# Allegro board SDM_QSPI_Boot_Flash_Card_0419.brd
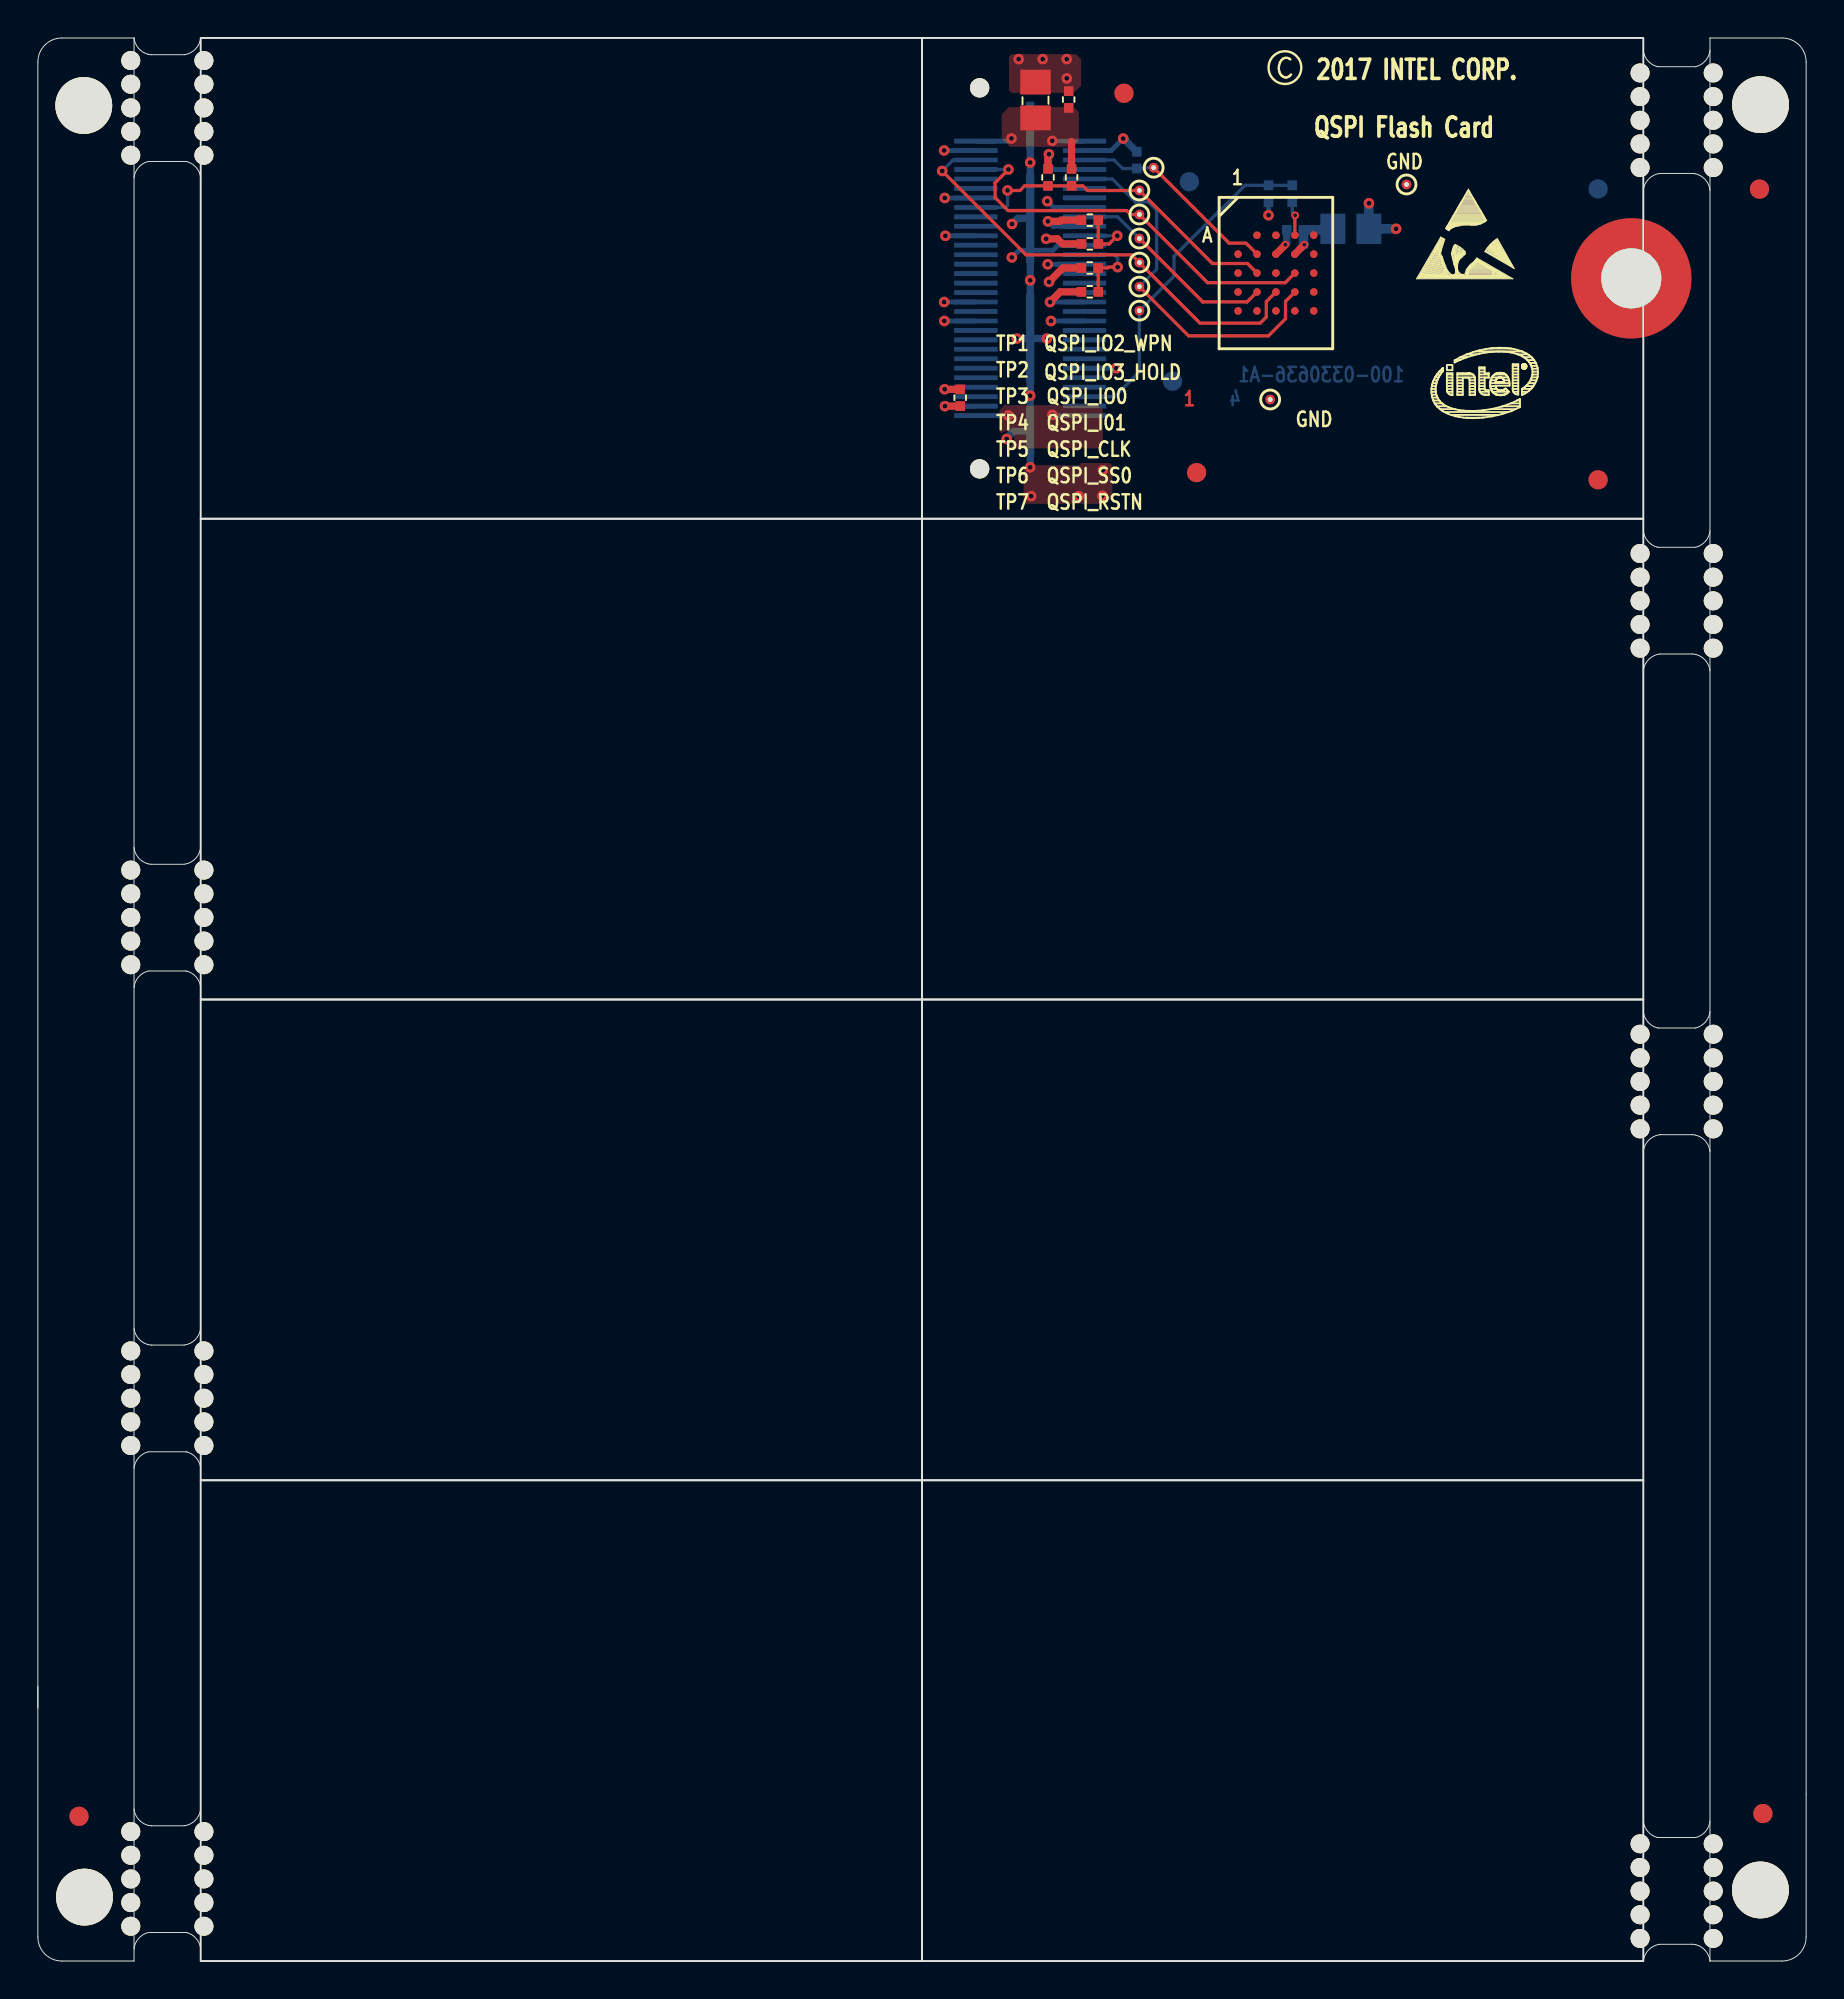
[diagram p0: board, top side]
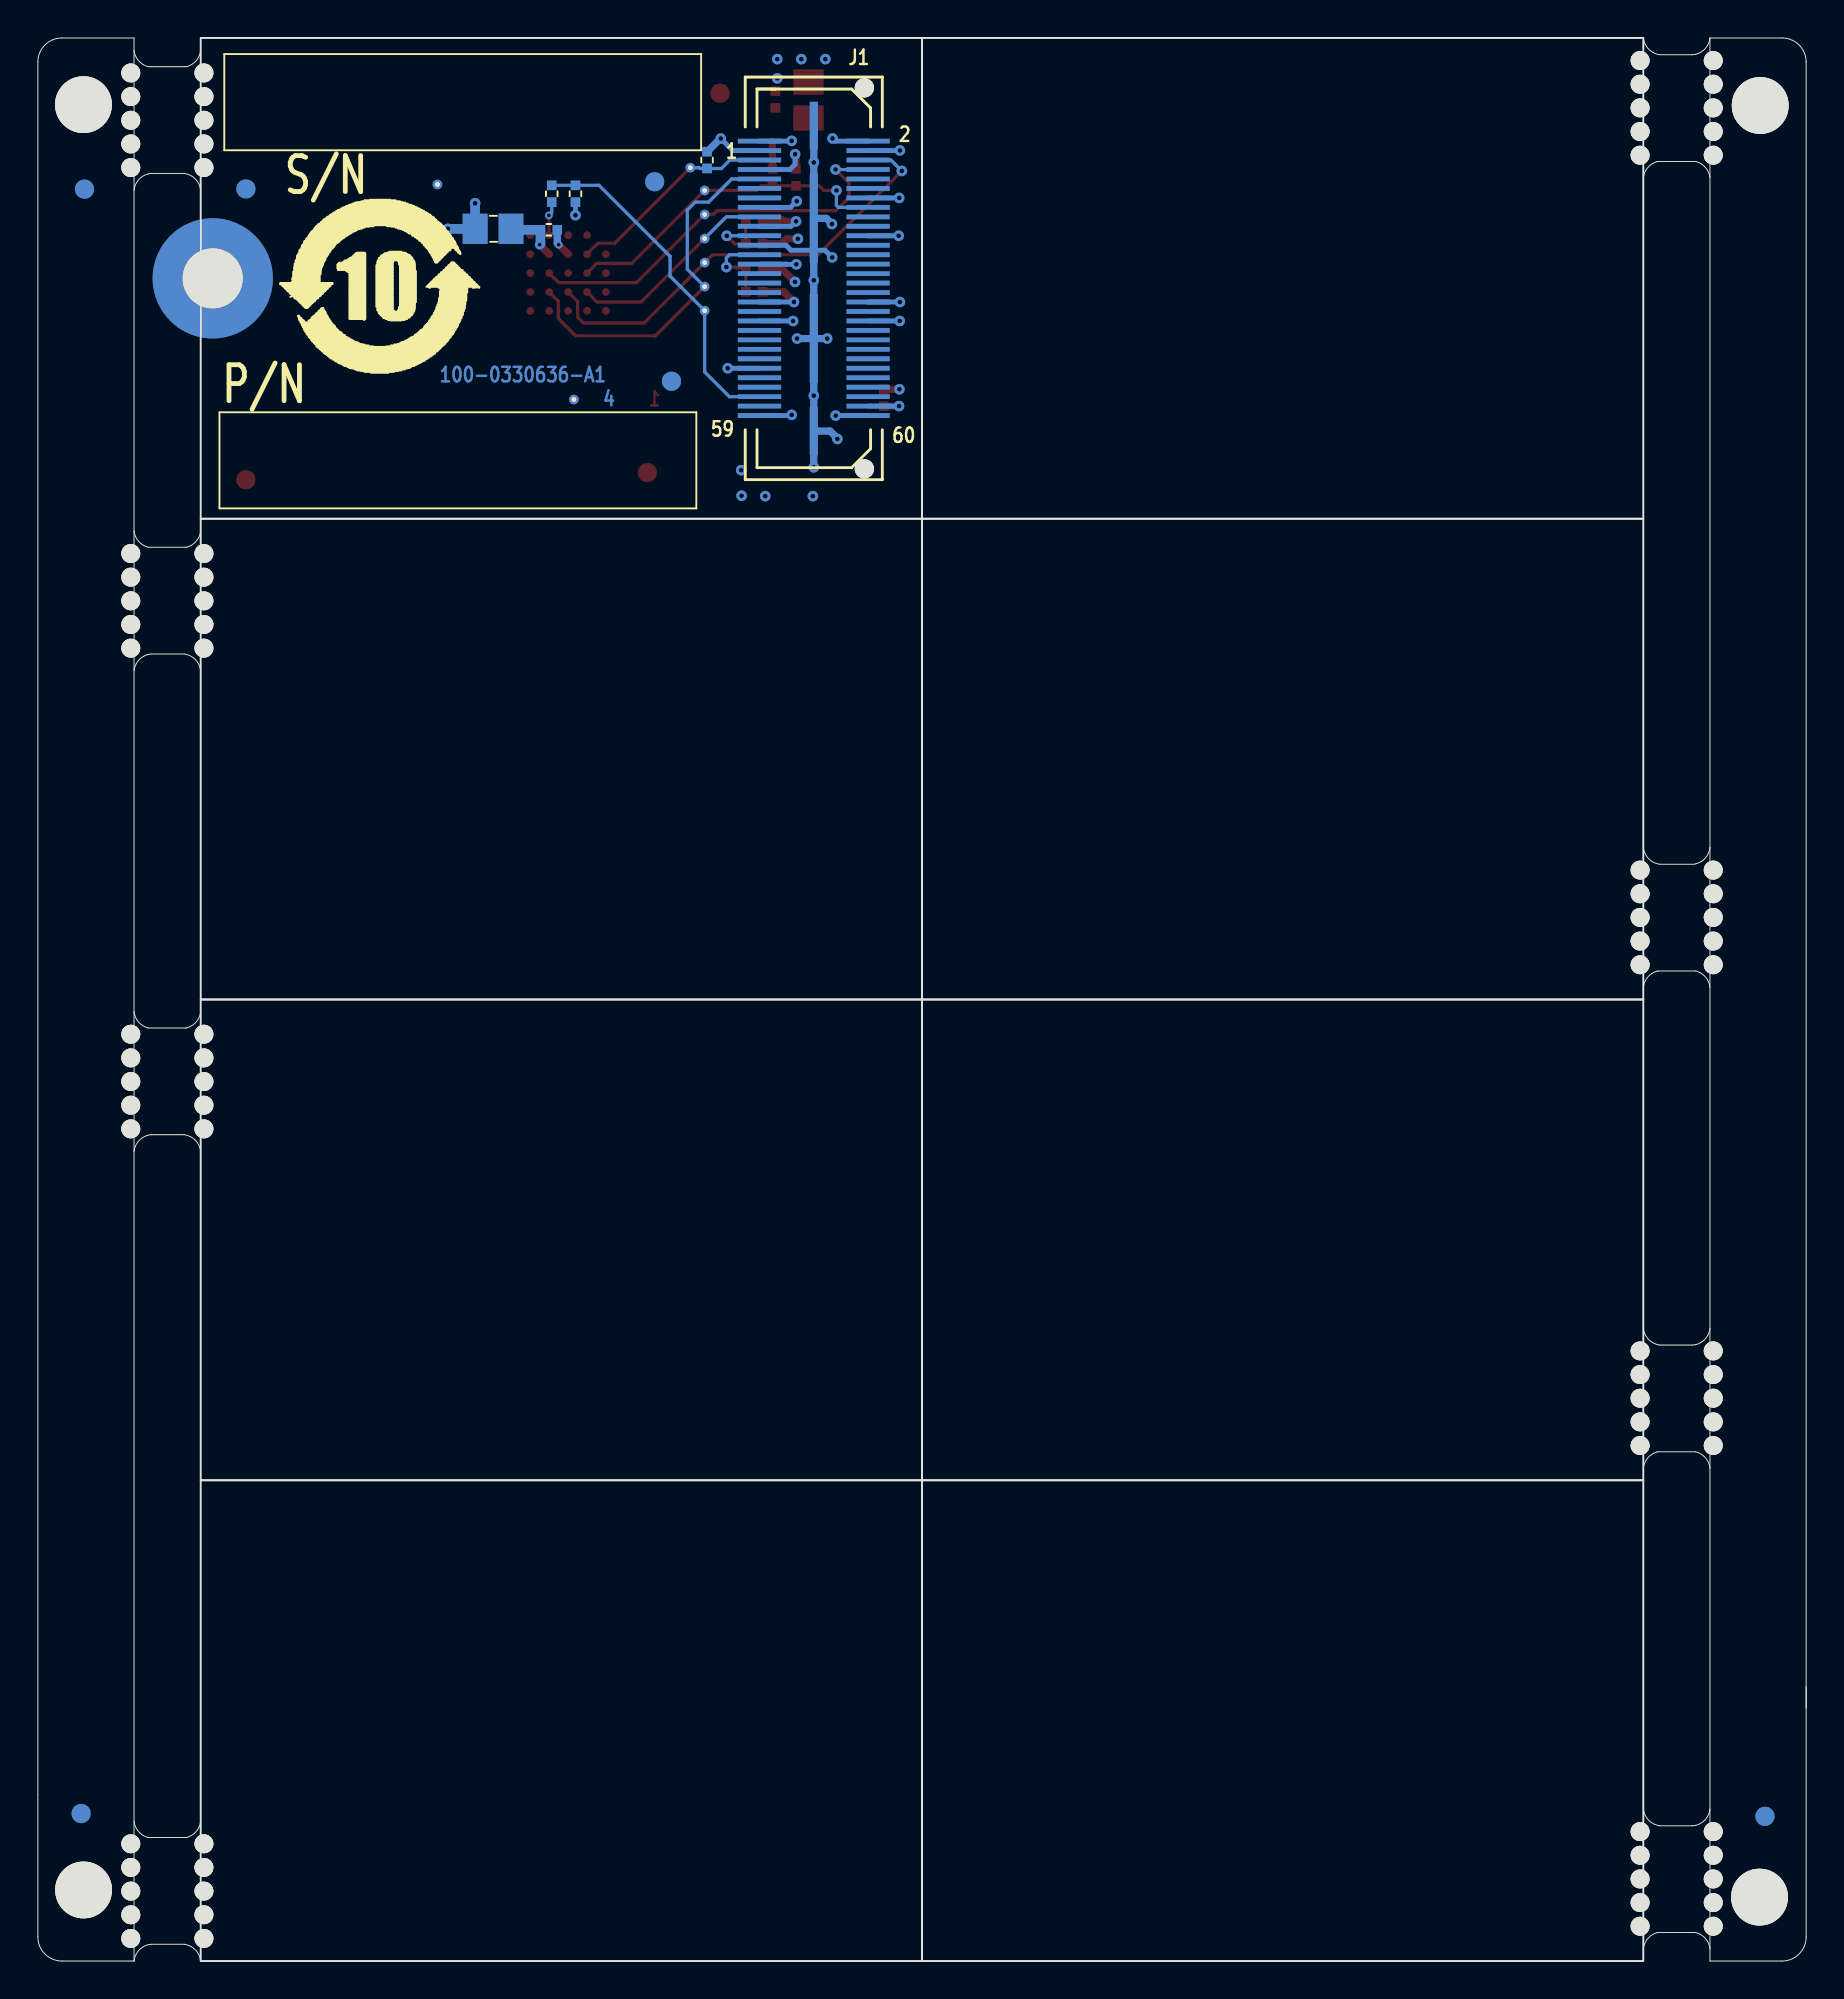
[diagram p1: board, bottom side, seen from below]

Outline 93.4 x 101.61 mm; copper layers: TOP, GND02, POWER03, BOTTOM. Coordinates in mm from the lower left corner of the outline.
Outline path: rectangle 8.6,76.21 46.7,101.61 ; rectangle 8.6,50.81 46.7,76.21 ; rectangle 8.6,25.41 46.7,50.81 ; rectangle 8.6,0.01 46.7,25.41 ; rectangle 46.7,76.21 84.8,101.61 ; rectangle 46.7,50.81 84.8,76.21 ; rectangle 46.7,25.41 84.8,50.81 ; rectangle 46.7,0.01 84.8,25.41 ; 0,13.37 0,100.34 arc(0.37,101.23) 1.27,101.61 5.08,101.61 5.08,0.01 1.27,0.01 arc(0.37,0.38) 0,1.28 0,14.51 ; 88.32,101.61 88.32,0.01 92.13,0.01 arc(93.03,0.38) 93.4,1.28 93.4,100.34 arc(93.03,101.23) 92.13,101.61 88.32,101.61

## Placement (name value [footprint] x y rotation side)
C1  4.7uF  [0805]  52.7 98.33 180 top
C2  0.1uF  [0402]  54.45 98.35 0 top
C3  4.7uF  [0805]  69.36 91.52 270 bottom
C4  0.1uF  [0402]  66.41 91.47 270 bottom
J1  -  [QSH-030-01-F-D-A]  52.42 88.91 270 bottom
NOREF  -  [unnamed]  90.94 93.62 0 top
NOREF#2  -  [unnamed#2]  6.08 29.74 270 top
NOREF#3  -  [unnamed]  2.46 3.38 180 top
NOREF#4  -  [unnamed#2]  6.08 55.14 270 top
NOREF#5  -  [unnamed]  82.41 78.26 0 top
NOREF#6  -  [unnamed#2]  87.33 71.87 90 top
NOREF#7  -  [unnamed]  91.12 7.8 0 top
NOREF#8  -  [unnamed#2]  6.08 4.34 270 top
NOREF#9  -  [unnamed#2]  87.33 46.47 90 top
NOREF#10  -  [unnamed]  57.37 98.69 0 top
NOREF#11  -  [unnamed]  61.2 78.64 0 top
NOREF#12  -  [#3]  451.73 -170.78 0 top
NOREF#13  -  [unnamed]  90.99 3.76 0 top
NOREF#14  -  [unnamed#2]  6.08 97.91 270 top
NOREF#15  -  [unnamed]  84.17 88.91 0 top
NOREF#16  -  [unnamed]  90.99 98.08 0 top
NOREF#17  -  [unnamed#2]  87.33 3.7 90 top
NOREF#18  -  [unnamed]  2.43 98.04 0 top
NOREF#19  -  [unnamed#2]  87.33 97.26 90 top
NOREF#20  -  [unnamed]  2.17 7.65 180 top
NOREF#21  -  [unnamed]  59.93 83.47 180 bottom
NOREF#22  -  [unnamed]  90.94 93.62 180 bottom
NOREF#23  -  [unnamed]  60.82 94.01 180 bottom
NOREF#24  -  [unnamed]  82.41 93.63 180 bottom
NOREF#25  -  [unnamed]  2.17 7.65 0 bottom
NOREF#26  -  [unnamed]  91.12 7.8 180 bottom
R1  10K  [0402]  65.01 93.38 180 bottom
R2  0  [0402]  66.26 93.38 180 bottom
R3  100K  [0402]  58.06 95.15 180 bottom
R4  0  [0402]  48.72 82.6 180 top
R5  DNI  [0402]  55.57 90.73 270 top
R6  DNI  [0402]  55.57 91.98 90 top
R7  DNI  [0402]  55.56 89.45 270 top
R8  DNI  [0402]  55.57 88.19 90 top
R9  DNI  [0402]  54.6 94.24 180 top
R10  DNI  [0402]  53.36 94.24 0 top
TP1  VIA_1  [TP_020RD_SMT]  58.18 92.28 0 top
TP2  VIA_1  [TP_020RD_SMT]  58.18 88.47 0 top
TP3  VIA_1  [TP_020RD_SMT]  58.18 89.74 0 top
TP4  VIA_1  [TP_020RD_SMT]  58.18 91.01 0 top
TP5  VIA_1  [TP_020RD_SMT]  58.94 94.75 0 top
TP6  VIA_1  [TP_020RD_SMT]  58.18 93.55 0 top
TP7  VIA_1  [TP_020RD_SMT]  58.18 87.2 0 top
TP8  VIA_1  [TP_020RD_SMT]  65.09 82.51 0 top
TP9  VIA_1  [TP_020RD_SMT]  72.29 93.87 0 top
U1  MT25QU02GCBB8E12-0SIT  [TBGA_24]  65.4 89.19 0 top

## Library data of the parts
C1 C3 = CAP: User Part Number: PART#; Tolerance: TOL
C2 C4 = CAP: Tolerance: TOL; User Part Number: PART#
J1 = QSH-030-01-F-D-A
R1 R2 R4-R10 = RESISTOR: Tolerance: TOL; User Part Number: PART#
R3 = RES 100K OHM 1.0% 1/16W 0402: Tolerance: TOL; User Part Number: PART#
TP1-TP9 = VIA_1
U1 = MT25QU01GBBA8E12-0SIT

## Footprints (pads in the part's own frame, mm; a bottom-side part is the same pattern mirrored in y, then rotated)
0402
  rect 0.508x0.508 smd: 1(0,0.445) 2(0,-0.445)
0805
  rect 1.6x1.321 smd: 1(0,0.95) 2(0,-0.95)
QSH-030-01-F-D-A
  round 1.016 hole 1.016 unplated: (-10.065,2.67) (10.065,2.67)
  rect 0.254x2.286 smd: 1(-7.25,-2.87) 2(-7.25,2.87) 3(-6.75,-2.87) 4(-6.75,2.87) 5(-6.25,-2.87) 6(-6.25,2.87) 7(-5.75,-2.87) 8(-5.75,2.87) 9(-5.25,-2.87) 10(-5.25,2.87) 11(-4.75,-2.87) 12(-4.75,2.87) 13(-4.25,-2.87) 14(-4.25,2.87) 15(-3.75,-2.87) 16(-3.75,2.87) 17(-3.25,-2.87) 18(-3.25,2.87) 19(-2.75,-2.87) 20(-2.75,2.87) 21(-2.25,-2.87) 22(-2.25,2.87) 23(-1.75,-2.87) 24(-1.75,2.87) 25(-1.25,-2.87) 26(-1.25,2.87) 27(-0.75,-2.87) 28(-0.75,2.87) 29(-0.25,-2.87) 30(-0.25,2.87) 31(0.25,-2.87) 32(0.25,2.87) 33(0.75,-2.87) 34(0.75,2.87) 35(1.25,-2.87) 36(1.25,2.87) 37(1.75,-2.87) 38(1.75,2.87) 39(2.25,-2.87) 40(2.25,2.87) 41(2.75,-2.87) 42(2.75,2.87) 43(3.25,-2.87) 44(3.25,2.87) 45(3.75,-2.87) 46(3.75,2.87) 47(4.25,-2.87) 48(4.25,2.87) 49(4.75,-2.87) 50(4.75,2.87) 51(5.25,-2.87) 52(5.25,2.87) 53(5.75,-2.87) 54(5.75,2.87) 55(6.25,-2.87) 56(6.25,2.87) 57(6.75,-2.87) 58(6.75,2.87) 59(7.25,-2.87) 60(7.25,2.87)
  rect 2.54x0.432 smd: G1(-8.06,0) G4(8.07,0)
  rect 4.699x0.432 smd: G2(-3.17,0) G3(3.18,0)
TBGA_24
  round 0.406 smd: A2(-1,2) A3(0,2) A4(1,2) A5(2,2) B1(-2,1) B2(-1,1) B3(0,1) B4(1,1) B5(2,1) C1(-2,0) C2(-1,0) C3(0,0) C4(1,0) C5(2,0) D1(-2,-1) D2(-1,-1) D3(0,-1) D4(1,-1) D5(2,-1) E1(-2,-2) E2(-1,-2) E3(0,-2) E4(1,-2) E5(2,-2)
TP_020RD_SMT
  round 0.508 hole 0.254: 1(0,0)
unnamed
  round 1.016 smd: (0,0)
unnamed#2
  round 1 hole 1 unplated: (-2.5,2.694) (-2.5,-1.17) (-1.25,2.694) (-1.25,-1.17) (0,2.694) (0,-1.17) (1.25,2.694) (1.25,-1.17) (2.5,2.694) (2.5,-1.17)

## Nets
1.8V: C1.1 C2.2 C3.1 C4.2 J1.1 J1.2 R1.2 R5.2 R7.2 R9.2 U1.B4(VCC)
3.3V: J1.59 J1.60
GND: C1.2 C2.1 C3.2 C4.1 J1.3 J1.4 J1.7 J1.14 J1.15 J1.19 J1.22 J1.23 J1.27 J1.35 J1.36 J1.39 J1.40 J1.49 J1.G1(GND#G1) J1.G2(GND#G2) J1.G3(GND#G3) J1.G4(GND#G4) R3.1 R4.2 R6.1 R8.1 R10.1 TP8.1(TP) TP9.1(TP) U1.B3(VSS)
BOOTSEL0: J1.21 R5.1 R6.2
BOOTSEL1: J1.25 R7.1 R8.2
CARD_PRSTN: J1.58 R4.1
QSPI_CLK: J1.5 R3.2 TP5.1(TP) U1.B2(C)
QSPI_IO0: J1.6 TP3.1(TP) U1.D3(DQ0)
QSPI_IO1: J1.17 TP4.1(TP) U1.D2(DQ1)
QSPI_IO2_WPN: J1.8 TP1.1(TP) U1.C4(DQ2/W#)
QSPI_IO3_HOLD: J1.9 TP2.1(TP) U1.D4(DQ3)
QSPI_RSTN: J1.55 R1.1 R2.1 TP7.1(TP)
QSPI_SS0: J1.16 R9.1 R10.2 TP6.1(TP) U1.C2(S#)
N16547222: R2.2 U1.A4(RESET#/DNU3)

Pads without a net: J1 10 11 12 13 18 20 24 26 28 29 30 31 32 33 34 37 38 41 42 43 44 45 46 47 48 50 51 52 53 54 56 57; U1 A2 A3 A5 B1 B5 C1 C3 C5 D1 D5 E1 E2 E3 E4 E5

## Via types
v1: diameter 0.559, hole 0.254, TOP to BOTTOM, 46 vias
v2: diameter 0.406, hole 0.203, TOP to BOTTOM, 3 vias

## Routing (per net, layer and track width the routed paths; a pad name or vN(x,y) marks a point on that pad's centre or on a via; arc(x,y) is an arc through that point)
1.8V: length 12.9
  TOP w0.381: R9.2 54.6,96.15 ; U1.B4 v2(66.9,90.69) ; R7.2 54.15,89.45 v1(53.41,88.72) ; R5.2 54.12,90.73 53.85,90.99 v1(53.26,90.99)
  BOTTOM w0.254: J1.2 51.28,96.16 v1(51.43,96.3) ; v1(53.58,96.17) 53.6,96.16 J1.1 ; R1.2 v1(65.01,92.24)
  BOTTOM w0.508: v2(66.9,90.69) 66.86,90.72 C4.2 68.36,91.47 C3.1
3.3V: length 3.4
  BOTTOM w0.254: v1(53.58,81.69) 53.62,81.66 J1.59 ; J1.60 v1(51.26,81.66)
GND: length 64.8
  TOP w0.381: R10.1 53.36,95.42 v1(53.4,95.46) ; R6.1 54.04,91.98 53.98,91.92 v1(53.35,91.92) ; U1.B3 v2(65.9,90.69) ; R8.1 54,88.19 v1(53.47,87.66) ; R4.2 v1(47.9,83.05)
  GND02 w0.17: 65.09,82.07 TP8.1 ; TP8.1 64.66,82.51 ; TP8.1 65.09,82.94 ; TP8.1 65.52,82.51 ; TP9.1 72.29,94.3 ; TP9.1 72.29,93.43 ; TP9.1 71.86,93.87 ; TP9.1 72.73,93.87
  BOTTOM w0.254: J1.15 53.65,92.66 v1(53.32,92.98) ; J1.19 53.62,91.66 v1(53.35,91.92) ; J1.35 53.47,87.66 v1(53.47,87.66) ; v1(53.51,86.65) 53.52,86.66 J1.39 ; J1.4 47.88,95.66 v1(47.87,95.66) ; J1.7 53.68,94.66 53.4,94.93 v1(53.4,95.46) ; v1(51.44,90.01) 51.82,90.39 53.62,90.39 53.89,90.66 J1.23 ; J1.22 v1(47.94,91.16) ; J1.40 v1(47.88,86.66) ; J1.49 v1(56.96,84.16) ; J1.14 v1(47.9,93.16) ; J1.27 53.88,89.66 53.87,89.65 v1(53.34,89.65) ; J1.36 v1(47.87,87.66) ; J1.3 56.69,95.66 v1(57.33,96.29)
  BOTTOM w0.381: 52.42,96.97 v1(52.42,95.03) J1.G2 ; C4.1 65.97,90.76 v2(65.9,90.69) ; J1.G3 v1(52.42,82.71) J1.G4 ; J1.G3 v1(53.3,85.73) ; J1.G3 v1(52.42,88.8) J1.G2 ; J1.G3 v1(51.71,85.73) ; v1(51.17,80.42) 51.17,80.46 51.55,80.84 J1.G4 ; J1.G4 v1(52.42,78.92) ; v1(57.33,96.29) 57.35,96.29 58.04,95.6 R3.1 ; J1.G2 51.76,92.08 v1(51.46,91.78)
  BOTTOM w0.508: v1(70.31,92.87) C3.2 v1(71.75,91.52)
  vias: v1(51.81,100.49) v1(52.47,77.4) v1(53.08,100.49) v1(54.35,100.49) v1(54.35,99.47) v1(54.98,77.4) v1(56.23,77.42) v1(56.25,78.77)
BOOTSEL0: length 4.2
  TOP w0.17: R6.2 R5.1 56.59,90.73 v1(57.02,91.16)
  BOTTOM w0.17: J1.21 v1(57.02,91.16)
BOOTSEL1: length 4.6
  TOP w0.17: R8.2 56.01,89.06 56.01,89.06 R7.1 56.5,89.45 56.54,89.5 v1(57.03,89.5)
  BOTTOM w0.17: v1(57.03,89.5) 57.03,89.98 56.86,90.16 J1.25
CARD_PRSTN: length 2.4
  TOP w0.381: R4.1 v1(47.91,82.16)
  BOTTOM w0.254: J1.58 v1(47.91,82.16)
QSPI_CLK: length 11.2
  TOP w0.17: U1.B2 63.82,90.76 62.93,90.76 TP5.1
  BOTTOM w0.17: TP5.1 58.47,94.75 58.43,94.71 R3.2 57.29,94.71 56.85,95.16 J1.5
QSPI_IO0: length 24.1
  TOP w0.17: U1.D3 64.89,87.68 64.89,86.86 64.57,86.54 61.38,86.54 TP3.1 57.77,90.15 52.2,90.15 v1(47.77,94.58)
  BOTTOM w0.17: v1(47.77,94.58) 48.34,95.16 J1.6
QSPI_IO1: length 11.2
  TOP w0.17: TP4.1 61.53,87.66 63.87,87.66 U1.D2
  BOTTOM w0.17: J1.17 57.04,92.16 TP4.1
QSPI_IO2_WPN: length 21.4
  TOP w0.17: v1(51.27,94.66) 50.56,93.95 50.56,93.18 51.25,92.49 57.52,92.49 57.72,92.28 TP1.1 61.79,88.67 65.89,88.67 U1.C4
  BOTTOM w0.17: J1.8 51.27,94.66 v1(51.27,94.66)
QSPI_IO3_HOLD: length 19.7
  TOP w0.17: U1.D4 65.9,87.69 65.9,86.77 65,85.87 60.78,85.87 TP2.1
  BOTTOM w0.17: TP2.1 59.1,89.38 59.1,92.51 58.67,92.93 57.97,92.93 56.75,94.16 J1.9
QSPI_RSTN: length 18.1
  BOTTOM w0.17: R2.1 R1.1 63.76,93.82 60.01,90.07 60.01,89.02 TP7.1 58.18,83.96 56.88,82.66 J1.55
QSPI_SS0: length 17.7
  TOP w0.17: U1.C2 63.89,89.69 62.04,89.69 TP6.1 55.44,93.55 55.19,93.8 R9.1 R10.2 52.13,93.8 51.88,93.55 v1(51.22,93.55)
  BOTTOM w0.17: J1.16 51.12,92.66 51.22,92.76 v1(51.22,93.55)
N16547222: length 1.8
  TOP w0.17: v2(66.41,92.23) 66.4,92.22 U1.A4
  BOTTOM w0.17: R2.2 66.26,92.39 v2(66.41,92.23)

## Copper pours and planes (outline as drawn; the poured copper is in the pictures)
1.8V on TOP: 50.92,96.28 50.92,97.57 51.3,97.95 54.73,97.95 54.98,97.69 54.98,96.15 54.69,95.86 54.69,95.86 51.34,95.86
1.8V on POWER03: 47.74,77.25 47.74,100.49 83.81,100.49 83.81,77.25
3.3V on TOP: 56,82.2 51.04,82.2 50.79,81.95 50.79,80.17 51.04,79.91 56.12,79.91 56.25,80.04 56.25,81.95
GND on TOP: 56.63,79.15 55.11,79.15 54.98,79.03 52.19,79.03 52.06,78.9 52.06,77.12 52.19,76.99 56.38,76.99 56.76,77.37 56.76,79.03
GND on TOP: 54.73,98.71 51.43,98.71 51.3,98.84 51.3,100.62 51.43,100.74 54.85,100.74 55.11,100.49 55.11,99.09
GND on GND02: 47.21,76.72 47.21,101.1 84.29,101.1 84.29,76.72

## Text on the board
BOTTOM: 4 | 100-0330636-A1
Ref Des/Silkscreen Bottom: PROPRIETARY NOTICE: | THIS DOCUMENT CONTAINS PROPRIETARY INFORMATION | OF INTEL CORP. NEITHER THE DOCUMENT NOR SAID | PROPRIETARY INFORMATION SHALL BE PUBLISHED, | REPRODUCED, COPIED, DISCLOSED OR USED FOR ANY | PURPOSE OTHER THAN CONSIDERATION OF THIS DOCUMENT | WITHOUT THE EXPRESS WRITTEN PERMISSION OF A DULY | AUTHORIZED REPRESENTATIVE OF INTEL CORPORATION | SECONDARY SIDE SHOWN | DWG NO. | 130-0330636-A1 | SIZE | SCALE: 1/1 | D | REV | A1 | CAGE CODE | N/A | SHEET 2 OF 2 | S/N | P/N
TOP: 1
Ref Des/Silkscreen Top: TP1 | TP2 | TP3 | TP4 | TP5 | TP6 | TP7 | QSPI_IO2_WPN | QSPI_IO3_HOLD | QSPI_IO0 | QSPI_I01 | QSPI_CLK | QSPI_SS0 | QSPI_RSTN | GND | QSPI Flash Card | 2017 INTEL CORP. | THIS DOCUMENT CONTAINS PROPRIETARY INFORMATION | OF INTEL CORP. NEITHER THE DOCUMENT NOR SAID | PROPRIETARY INFORMATION SHALL BE PUBLISHED, | REPRODUCED, COPIED, DISCLOSED OR USED FOR ANY | PURPOSE OTHER THAN CONSIDERATION OF THIS DOCUMENT | WITHOUT THE EXPRESS WRITTEN PERMISSION OF A DULY | AUTHORIZED REPRESENTATIVE OF INTEL CORPORATION | PROPRIETARY NOTICE: | DASH | PROJECTION | XX-XXX-XXXX | NEXT ASSY | APPLICATION | UNLESS OTHERWISE SPECIFIED: | DIMENSIONS ARE IN INCHES IN | ACCORDANCE WITH ANSI Y14.5. | DRILL TOLERANCES ARE PER 10387 | USED ON | SPEC | FNSH | TOLERANCES: | DEC .XXXX  .002 | DEC .X | DEC .XX   .01 | DEC .XXX  .005 | FRACTIONS | ANGLES    1 | + | - | o | CHKR | RELEASE | DWN | DSGN ENGR | CONTRACT NO. | DWG NO. | PSG Board Design Team | 130-0330636-A1 | XXXXXXXX | REV | 1-April-2017 | SIZE | TITLE | D | SCALE: 1/1 | A1 | DESCRIPTION | CAGE CODE | N/A | REVISIONS | SDM QSPI Boot Flash Daughter Card | PCB ASSEMBLY | DATE | SHEET 1 OF 1 | APPROVED | 19 | 8 | 3 | 21 | 23 | SAN JOSE, CA 95134 | 101 INNOVATION DRIVE | (c) 2017 INTEL Corporation | NOTES: UNLESS OTHERWISE SPECIFIED | 8.  INSTALL BAR CODE LABEL APPROX WHERE SHOWN, INCLUDING S/N. | 1.  ASSEMBLY HOUSE TO VISUALLY VERIFY BOARD BEING ASSEMBLED HAS | 2.  BOARDS MUST BE BAKED FOR A DURATION OF 8 HOURS AT 250 DEGREES | FARENHEIT IMMEDIATELY PRIOR TO ASSEMBLY. | 3.  ASSEMBLE BOARD PER IPC-A-610(LATEST REVISION) STANDARD. | 4.  ALL MATERIALS USED MUST BE RoHS COMPLIANT. | 5.  HANDLE MOISTURE SENSITIVE DEVICES(MSD) PER MANUFACTURE'S | CALL OUT ON MSD LABEL.  IF MSD LABEL IS MISSING OR NOT LEGIBLE | 6.  REWORK MUST BE APPROVED BY CUSTOMER BEFORE BEING ACCEPTIBLE | USE IPC-R-700(LATEST REVISION) FOR ALL PCA REWORK APPROVED. | 7.  SQUARE PIN PAD DENOTE PIN 1 OF ICs/CONNECTORS, POSITIVE END | FOR CAPACITORS OR CATHODE END FOR DIODES. | 9.  VENDOR TO KEEP QUALITY CONTROL INK STAMPINGS OFF SIGNAL TRACES | AND PADS EVEN IF COVERED BY SOLDERMASK. | INTEL P/N 100-0330636-A1 IN ETCH ON BOTTOM SIDE. | THEN ALL PLASTIC PACKAGED COMPONENTS ARE TO BE CONSIDERED MSD | LEVEL 6 AND USE EIA/JEP 113-A FOR HANDLING. | PRIMARY SIDE SHOWN
GND02: 2
POWER03: 3
DIMENSION: Note:If etch layer don't have  above impedance track pls ignore | +/-10% | * | Hoz+Plating | 1OZ | L1\L4 | 6.7 | 50 | PP(2116) | Core | L2;L3 | Via  Technic: | Spell Mode: | Bow and Twist Tolerance:<=0.70% | Inspectionstandard: | Compare With IPC File: | (unit:mil)MIN.track :                       MIN.spacing :                 MIN.hole: | Outline Profile: | Fast Print Logo: | Silk Screen Colours: | Dielectric Material: | Soldermask Colours: | Surface Finished: | Finger Chamfer: | 5.5 | Hasl Lead Free | Yes | Green | White | Router | Hasl | Required | All via (<=0.5mm) must be filled(except open soldermask via) | IPCII | Pressfit holes: The tolerance of                 is+/-0.05mm | Angle | Board Thickness(MM): | Specified Position | IPCIII | 20 | Bridge | Immersion Tin | No | Yellow | Flash Gold | Blue | Open Windows: | 5 | Matte Green | Black | Immersion Gold | Immersion Silver | 30 | GJB362B | V-cut | Only Date Code | None | Layers: | Gold Finger | Other | 45 | 10 | By gerber | Not Appear | Stamp Hole | QJ831B | Osp | 1.6 | 4 | 4.438(mil) | 44.882(mil) | 1.  STACKING (dielectric thickness can be adjusted beween +/-2mil,but don,t less than 3.5mil; | IF inspection is GJB362B or QJ831B then don,t less than 4mil.) | 2.  Control Impedance (track width can be adjusted +/-0.5mil , but don,t less than 4mil.) | ref layer | Board Name: | Lead Time: | SSC PN: | PSG Board Design Team | Purchase   Order &  Specification   Sheet | TOP | GND02 | PWR03 | BOTTOM | PROPRIETARY NOTICE: | THIS DOCUMENT CONTAINS PROPRIETARY INFORMATION | OF INTEL CORP. NEITHER THE DOCUMENT NOR SAID | PROPRIETARY INFORMATION SHALL BE PUBLISHED, | REPRODUCED, COPIED, DISCLOSED OR USED FOR ANY | PURPOSE OTHER THAN CONSIDERATION OF THIS DOCUMENT | WITHOUT THE EXPRESS WRITTEN PERMISSION OF A DULY | AUTHORIZED REPRESENTATIVE OF INTEL CORPORATION | DASH | THIRD ANGLE | PROJECTION | XX-XXX-XXXX | NEXT ASSY | APPLICATION | UNLESS OTHERWISE SPECIFIED: | DIMENSIONS ARE IN INCHES IN | ACCORDANCE WITH ANSI Y14.5. | DRILL TOLERANCES ARE PER 10387 | USED ON | SPEC | FNSH | MATL | EE: | DATE: | [c]2017 Intel Corporation | April-1-2017 | 101 INNOVATION DRIVE | SAN JOSE, CA. 95134 | TOLERANCES: | DESIGNER: | SHEET | DEC .XXXX  .002 | OF 1 | DEC .X | DEC .XX   .01 | DEC .XXX  .005 | FRACTIONS | ANGLES    1 | TITLE | FILM TITLE | + | - | DOCUMENT NUMBER | SDM QSPI Boot Flash Daughter Card | 140-0330636-A1 | o | CHKR | RELEASE | DWN | DSGN ENGR | CONTRACT NO. | DWG NO. | XXXXXXXX | REV | 1-April-2017 | A1 | SIZE | D | SCALE: 1/1 | CAGE CODE | N/A | DESCRIPTION | REVISIONS | PCB FABRICATION | DATE | SHEET 1 OF 1 | APPROVED | 19 | 8 | 3 | 21 | 23 | (c) 2017 INTEL Corporation | SAN JOSE, CA 95134 | (LATEST REVISION). | NOTES UNLESS OTHERWISE SPECIFIED: | 1. PCB VENDOR MUST NOTIFY RESPONSIBLE INTEL PCB CONTACT OF ANY DISCREPANCIES | FOUND BETWEEN FABRICATION DATA AND FABRICATION DRAWING NOTES. | 2. THIS DRAWING IS VIEWED FROM THE PRIMARY OR TOP SIDE OF THE PCB. | 3  FABRICATION OF THIS PCB SHALL BE IN CONFORMANCE WITH THE FOLLOWING | SPECIFICATIONS: IPC-6011 CLASS 2 (GENERIC). | 4. ALL MATERIALS USED MUST BE RoHS COMPLIANT. | 5. FABRICATION OF THIS PCB TO BE ACCEPTABLE TO IPC-A-600 CLASS 2 | 6. ALL DIMENSIONAL LIMITS APPLY AFTER PLATING OR PROCESSING. | 7. TOLERANCES OF DATUM HOLE TO:  BOARD EDGE LOCATIONS +/- 0.010. | DRILLED HOLE LOCATIONS +/- 0.003. | V-SCORE LOCATIONS +/- 0.010 | 8  BASE MATERIAL: IT180A PP (2116) | 9. FLAME CLASS: UL 94V-0 & MUST MEET REQUIREMENTS OF UL796. | 10. MANUFACTURER MUST BE UL RECOGNIZED TO PRODUCE THIS PRODUCT SUCH THAT | 11  THE FOLLOWING MUST BE MARKED OR ETCHED ON SECONDARY SIDE OF PCB IN AREA | SHOWN: | a)  DATE CODE. | b)  UL RECOGNIZED VENDOR ID, UL TYPE DESIGNATION AND/OR MARKINGS WHICH | REFLECT THE SPECIFIED FLAME CLASS AND MAXIMUM OPERATING TEMPERATURE | RATINGS. | 12. PCB VENDOR TO ENSURE ALL UNCONNECTED (NON-FUNCTIONAL) INTERNAL SIGNAL | LAYER PADS AND VIAS ARE REMOVED. | 13. HOLE/SLOT PLATING = 0.001 MIN. AVERAGE / 0.0008 ABSOLUTE MIN. PLATING. | HOLE/SLOT DIAMETERS ARE SPECIFIED AFTER PLATING (SEE HOLE SCHEDULE). | 14  THESE VIA IN PAD MUST BE VIA FILLED USING NON-CONDUCTIVE | 15. AFTER REVIEWING FABRICATION DATA, PCB VENDOR MUST DISCUSS WHETHER COPPER | THIEVING IS NECESSARY WITH THE RESPONSIBLE INTEL PCB CONTACT.  WHEN | DETERMINED NECESSARY.  A SPACING OF 100 MILS FROM ANY OTHER COPPER FEATURE | ON THE BOARD MUST BE MAINTAINED. | 16. SMEAR REMOVAL SHALL NOT ETCHBACK GREATER THAN 0.001. | 17. FINISHED CONDUCTOR WIDTH NOT TO BE REDUCED MORE THAN 20% OF MINIMUM WIDTH | FROM ARTWORK SUPPLIED. FINISHED CONDUCTOR SPACING NOT TO BE REDUCED MORE | THAN 20% OF MINIMUM SPACING FROM ARTWORK SUPPLIED. | 18. TEAR DROPPING OF TRACE TO PAD JUNCTION IS PERMITTED PROVIDED MINIMUM | METAL-TO-METAL ARTWORK SPACINGS ARE NOT COMPROMISED. | 19  SOLDER MASK IS LIQUID PHOTO IMAGEABLE AND IN ACCORDANCE WITH IPC-SM-840C | CLASS T.  FINISH MUST BE GREEN AND GLOSSY. REGISTRATION TO BE WITHIN | +/- 0.003 OF ITS RESPECTIVE OUTER CIRCUIT LAYERS. VENDOR MAY ADJUST | SOLDERMASK WHEREVER SOLDERMASK PADS ARE THE SAME SIZE (1:1) TO PROVIDE UP | TO .003 MAXIMUM CLEARANCE FROM MASK TO PAD PROVIDED NO ADJACENT COPPER IS | EXPOSED AND NO CONFLICT IS PRODUCED WITH ANY STATED "VIA TENTING/PLUGGING" | REQUIREMENTS. | 20  PCB VENDOR TO ENSURE VIAS ARE SOLDERMASK ENCROACHED ON BOTTOM SIDE OF | PCB, EXCEPT IN AREAS SHOWN DUE TO BOTTOM MOUNT BGA PACKAGES. | 21  PCB FINISH BOTH SIDES TO BE ELECTROLESS NICKEL (Ni) FOLLOWED BY IMMERSION | GOLD (AU) (ENIG) ACCEPTABLE TO IPC-4552. | 22. REMOVE ALL SHARP EDGES AND BURRS 0.003" MAXIMUM. | 23  SILKSCREEN USING WHITE NONCONDUCTIVE INK. NO INK TO APPEAR ON EXPOSED | COPPER SUCH AS PLATED THROUGH HOLE PADS AND SURFACE MOUNT LANDS. INK | ON SOLDER MASK COVERED PADS IS PERMISSIBLE. CLIPPING OF SILKSCREEN | 0.008 MAX. FROM PADS IS PERMITTED. | 24. BOW & TWIST SHALL BE DETERMINED BY PHYSICAL MEASUREMENT AND PERCENTAGE | CALCULATION IN ACCORDANCE WITH IPC-TM-650, METHOD 2.4.22. BOW AND TWIST | MAY NOT EXCEED 0.7% | 25. 100% CONTINUITY AND ISOLATION ELECTRICAL TESTING PER CURRENT IPC TEST | METHODS REQUIRED FOR EVERY PCB. FINAL PCB TEST DATA MUST BE CROSS- | REFERENCED TO IPC-D-356 FILE, NEUTRAL FILE OR NETLIST PROVIDED. | 26. PCB VENDOR TO PROVIDE ONE TEST COUPON AND ONE CROSS SECTION PER LOT WITH | SHIPMENT. | 27. PCB VENDOR TO PROVIDE 2 SOLDER SAMPLES WITH FIRST SHIPMENT. | 28  VENDOR TO KEEP QUALITY CONTROL INK STAMPINGS ON BOTTOM OF PCB IN AREA | SPECIFIED.  STAMPINGS CANNOT BE ON TRACES OR PADS EVEN IF COVERED BY MASK. | 29. DETAILS NOT SPECIFIED ARE AT MANUFACTURER'S OPTION, HOWEVER | FINAL APPROVAL MUST BE OBTAINED. | IT MEETS 130 DEGREES CELSIUS MAXIMUM OPERATING TEMPERATURE (MOT). | EPOXY VIA FILL, PLANARIZED AND PLATED OVER.
User.45: FIGURE | SIZE | 8.0 | 10.0 | 125.0 | 39.37 | 40.0 | 118.11 | DRILL CHART: TOP to BOTTOM | ALL UNITS ARE IN MILS | PLATED | NON-PLATED | QTY | 3 | 46 | 9 | 1 | 80 | 2 | 4
